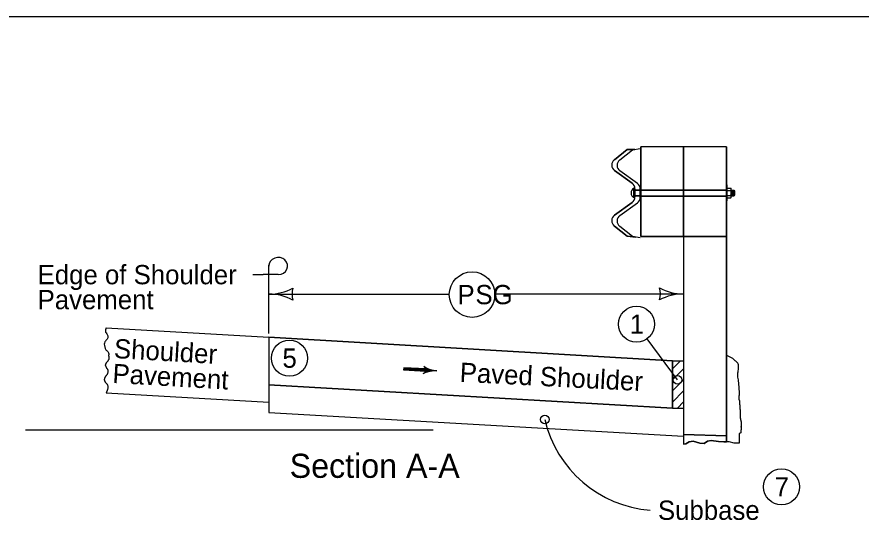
# Model space of a CAD drawing. Extents: x 8045 to 81668, y 6217 to 16762.
# Drawn here: x 10335 to 11036, y 8939 to 9356 of the extents above; entities that cross this region are included whole.
import ezdxf

# ---------------------------------------------------------------- set-up
doc = ezdxf.new("R2010")
doc.units = 0
for name, color, linetype in [('dsnStdDetailExtension', 7, 'Continuous'), ('dsnStdLabel', 7, 'Continuous'), ('dsnStdLineWork', 7, 'Continuous'), ('dsnStdPattern', 7, 'Continuous'), ('Level 4', 7, 'Continuous'), ('Level 8', 7, 'Continuous'), ('TextBlockOut', 7, 'Continuous')]:
    doc.layers.add(name, color=color, linetype=linetype)

msp = doc.modelspace()

# ---------------------------------------------------------------- linework, layer by layer
at = {"layer": 'dsnStdDetailExtension'}
msp.add_circle((10773.25, 9022.18), 3.54, dxfattribs=at)
msp.add_circle((10773.25, 9022.18), 3.54, dxfattribs=at)
at = {"layer": 'dsnStdLabel'}
for p, q in [((10924.05, 9248.59), (10852.96, 9248.59)), ((10852.96, 9173.94), (10852.96, 9248.59)), ((10888.5, 9173.94), (10888.5, 9248.59)), ((10924.05, 9248.59), (10924.05, 9003.55)), ((10831.02, 9237.83), (10841.78, 9246.23)), ((10835.45, 9237.6), (10846.22, 9246.01)), ((10841.78, 9246.23), (10848.11, 9246.34)), ((10846.22, 9246.01), (10852.56, 9247.12)), ((10845.72, 9218.29), (10831.21, 9228.71)), ((10850.19, 9218.06), (10835.63, 9228.51)), ((10847.34, 9206.19), (10847.34, 9214.27)), ((10848.12, 9206.85), (10848.11, 9213.66)), ((10852.56, 9210.04), (10852.56, 9213.44)), ((10924.05, 9216.88), (10924.73, 9216.88)), ((10924.73, 9203.55), (10924.73, 9216.88)), ((10924.73, 9214.26), (10927.7, 9214.26)), ((10847.34, 9212.58), (10852.77, 9212.58)), ((10847.34, 9207.91), (10852.96, 9207.91)), ((10848.11, 9206.85), (10848.12, 9210.26)), ((10848.12, 9210.26), (10848.12, 9206.85)), ((10848.29, 9212.58), (10852.96, 9212.58)), ((10852.56, 9206.63), (10852.56, 9210.04)), ((10852.56, 9210.04), (10852.56, 9206.63)), ((10852.95, 9207.58), (10924.05, 9207.58)), ((10852.96, 9212.91), (10924.05, 9212.91)), ((10852.96, 9212.58), (10924.05, 9212.58)), ((10852.96, 9207.91), (10924.05, 9207.91)), ((10924.73, 9212.24), (10927.7, 9212.24)), ((10924.73, 9208.2), (10927.7, 9208.2)), ((10928.06, 9207.19), (10928.06, 9213.25)), ((10928.06, 9212.55), (10930.43, 9212.55)), ((10928.06, 9207.89), (10930.43, 9207.89)), ((10928.95, 9212.55), (10928.95, 9207.89)), ((10929.69, 9212.55), (10929.69, 9207.89)), ((10930.43, 9212.55), (10930.88, 9212.02)), ((10930.43, 9212.55), (10930.43, 9207.89)), ((10930.88, 9208.42), (10930.43, 9207.89)), ((10930.88, 9212.02), (10930.88, 9208.42)), ((10831.21, 9191.8), (10845.72, 9202.22)), ((10835.63, 9191.56), (10850.19, 9202.02)), ((10924.05, 9203.55), (10924.73, 9203.55)), ((10924.73, 9206.18), (10927.7, 9206.18)), ((10841.78, 9174.29), (10831.02, 9182.68)), ((10846.22, 9174.07), (10835.45, 9182.48)), ((10848.88, 9173.6), (10841.78, 9174.29)), ((10852.56, 9172.95), (10846.22, 9174.07)), ((10888.5, 9173.94), (10852.96, 9173.94)), ((10888.5, 9173.94), (10888.5, 9001.71)), ((10408.97, 9098.32), (10544.11, 9090.46)), ((10544.11, 9090.46), (10544.11, 9036.45)), ((10544.11, 9090.46), (10879.25, 9070.97)), ((10879.25, 9064.23), (10885.99, 9070.97)), ((10879.25, 9064.23), (10885.99, 9070.97)), ((10879.25, 9064.23), (10885.99, 9070.97)), ((10879.25, 9064.23), (10885.99, 9070.97)), ((10879.25, 9070.97), (10888.49, 9070.97)), ((10879.25, 9070.97), (10879.25, 9031.55)), ((10879.25, 9055.04), (10888.49, 9064.28)), ((10879.25, 9055.04), (10888.49, 9064.28)), ((10879.25, 9055.04), (10888.49, 9064.28)), ((10879.25, 9055.04), (10888.49, 9064.28)), ((10934.1, 9064.21), (10934.1, 9064.21)), ((10879.25, 9045.82), (10888.49, 9055.05)), ((10879.25, 9045.82), (10888.49, 9055.05)), ((10879.25, 9045.82), (10888.49, 9055.05)), ((10879.25, 9045.82), (10888.49, 9055.05)), ((10879.25, 9031.55), (10544.11, 9050.86)), ((10879.25, 9036.59), (10888.49, 9045.83)), ((10409, 9044.31), (10544.11, 9036.45)), ((10544.11, 9036.45), (10544.11, 9028.03)), ((10879.25, 9031.55), (10888.49, 9031.55)), ((10883.35, 9031.55), (10888.49, 9036.68)), ((10544.11, 9028.03), (10888.5, 9008.17)), ((10342.06, 9013.62), (10680.56, 9013.62))]:
    msp.add_line(p, q, dxfattribs=at)
for points in [[(10928.05, 9207.51), (10928, 9207.78), (10927.96, 9207.95), (10927.87, 9208.11), (10927.75, 9208.2), (10927.83, 9208.3), (10927.91, 9208.52), (10927.97, 9208.83), (10928.05, 9209.58), (10928.05, 9207.51), (10928.03, 9207.65), (10927.99, 9207.87), (10927.91, 9208.08), (10927.79, 9208.19), (10927.83, 9208.28), (10927.89, 9208.42), (10927.99, 9208.93), (10928.03, 9209.31), (10928.03, 9207.7), (10928, 9207.82), (10927.96, 9207.98), (10927.83, 9208.19), (10927.88, 9208.36), (10927.96, 9208.69), (10928.02, 9209.02), (10928.01, 9207.86), (10927.97, 9207.98), (10927.86, 9208.18), (10927.9, 9208.39), (10927.96, 9208.65), (10927.99, 9208.82), (10927.99, 9207.96), (10927.93, 9208.07), (10927.88, 9208.18), (10927.97, 9208.64), (10927.97, 9208.04), (10927.9, 9208.18), (10927.95, 9208.47), (10927.95, 9208.12), (10927.92, 9208.19), (10927.93, 9208.29), (10927.93, 9208.21)], [(10927.76, 9212.24), (10927.83, 9212.28), (10927.91, 9212.39), (10927.99, 9212.61), (10928.05, 9212.89), (10928.05, 9210.95), (10927.99, 9211.46), (10927.94, 9211.83), (10927.82, 9212.16), (10927.76, 9212.24), (10927.82, 9212.25), (10927.92, 9212.39), (10928.01, 9212.62), (10928.03, 9212.77), (10928.03, 9211.24), (10927.96, 9211.73), (10927.9, 9211.99), (10927.8, 9212.22), (10927.83, 9212.23), (10927.97, 9212.45), (10928.01, 9212.6), (10928.01, 9211.49), (10927.82, 9212.21), (10927.99, 9212.48), (10927.99, 9211.63), (10927.85, 9212.19), (10927.97, 9212.42), (10927.98, 9211.78), (10927.87, 9212.18), (10927.96, 9212.35), (10927.96, 9211.94), (10927.89, 9212.16), (10927.94, 9212.28), (10927.94, 9212.08), (10927.91, 9212.15), (10927.92, 9212.19)], [(10934.57, 9040.37), (10934.51, 9040.09), (10934.51, 9039.9), (10934.51, 9039.7), (10934.51, 9039.51), (10934.51, 9039.31), (10934.51, 9039.12), (10934.51, 9038.82), (10934.51, 9038.63), (10934.61, 9038.34), (10934.71, 9038.04), (10934.9, 9037.85), (10934.9, 9037.65), (10935, 9037.46), (10935, 9037.26), (10935, 9037.06), (10935.1, 9036.97), (10935.1, 9036.77), (10935.1, 9036.58), (10935.1, 9036.38), (10935.1, 9036.19), (10935.1, 9035.99), (10935.1, 9035.7), (10935.1, 9035.4), (10935.1, 9035.21), (10935.1, 9034.92), (10935.1, 9034.72), (10935.1, 9034.52), (10935.2, 9034.43), (10935.2, 9034.23), (10935.2, 9034.04), (10935.2, 9033.84), (10935.2, 9033.65), (10935.2, 9033.45), (10935.2, 9033.25), (10935.2, 9033.06), (10935.2, 9032.86), (10935.2, 9032.67), (10935.2, 9032.47), (10935.2, 9032.28), (10935.2, 9032.08), (10935.2, 9031.89), (10935.2, 9031.69), (10935.2, 9031.5), (10935.2, 9031.3), (10935.2, 9031.1), (10935.2, 9030.91), (10935.29, 9030.81), (10935.29, 9030.62), (10935.29, 9030.42), (10935.39, 9030.32), (10935.39, 9030.13), (10935.39, 9029.93), (10935.49, 9029.83), (10935.49, 9029.64), (10935.49, 9029.44), (10935.49, 9029.25), (10935.49, 9028.96), (10935.59, 9028.66), (10935.59, 9028.47), (10935.59, 9028.27), (10935.59, 9028.08), (10935.59, 9027.88), (10935.59, 9027.69), (10935.59, 9027.49), (10935.59, 9027.29), (10935.59, 9027.1), (10935.59, 9026.9), (10935.59, 9026.71), (10935.59, 9026.51), (10935.59, 9026.32), (10935.59, 9026.12), (10935.59, 9025.93), (10935.59, 9025.73), (10935.59, 9025.54), (10935.59, 9025.34), (10935.59, 9025.14), (10935.59, 9024.95), (10935.59, 9024.75), (10935.59, 9024.56), (10935.59, 9024.36), (10935.59, 9024.17), (10935.59, 9023.97), (10935.59, 9023.78), (10935.59, 9023.58), (10935.59, 9023.39), (10935.59, 9023.19), (10935.59, 9023), (10935.68, 9022.9), (10935.68, 9022.6), (10935.68, 9022.41), (10935.78, 9022.21), (10935.88, 9021.92), (10935.88, 9021.73), (10935.98, 9021.63), (10935.98, 9021.43), (10936.07, 9021.33), (10936.17, 9021.24), (10936.17, 9021.04), (10936.17, 9020.85), (10936.17, 9020.65), (10936.27, 9020.55), (10936.27, 9020.36), (10936.27, 9020.16), (10936.27, 9019.97), (10936.27, 9019.77), (10936.27, 9019.58), (10936.27, 9019.38), (10936.27, 9019.19), (10936.27, 9018.99), (10936.27, 9018.79), (10936.27, 9018.6), (10936.27, 9018.4), (10936.27, 9018.21), (10936.27, 9018.01), (10936.27, 9017.82), (10936.27, 9017.62), (10936.27, 9017.43), (10936.27, 9017.23), (10936.27, 9017.04), (10936.27, 9016.84), (10936.27, 9016.64), (10936.27, 9016.45), (10936.27, 9016.25), (10936.27, 9016.06), (10936.27, 9015.86), (10936.27, 9015.67), (10936.27, 9015.67), (10936.27, 9015.96), (10936.27, 9016.16), (10936.27, 9016.35), (10936.27, 9016.16), (10936.27, 9015.96), (10936.27, 9015.77), (10936.27, 9015.57), (10936.27, 9015.37), (10936.27, 9015.18), (10936.27, 9014.98), (10936.27, 9014.79), (10936.27, 9014.59), (10936.27, 9014.4), (10936.27, 9014.2), (10936.27, 9014.01), (10936.27, 9013.81), (10936.27, 9013.62), (10936.27, 9013.42), (10936.17, 9013.32), (10936.17, 9013.13), (10936.17, 9012.93), (10936.17, 9012.74), (10936.17, 9012.54), (10936.17, 9012.35), (10936.17, 9012.15), (10936.17, 9011.95), (10936.17, 9011.76), (10936.17, 9011.56), (10936.17, 9011.37), (10936.07, 9011.27), (10935.98, 9011.08), (10935.88, 9010.98), (10935.78, 9010.88), (10935.68, 9010.78), (10935.49, 9010.68), (10935.29, 9010.68), (10935.2, 9010.59), (10935.1, 9010.49), (10935, 9010.39), (10934.8, 9010.29), (10934.71, 9010.2), (10934.71, 9010), (10934.61, 9009.9), (10934.61, 9009.71), (10934.61, 9009.51), (10934.61, 9009.32), (10934.61, 9002.5)], [(10934.74, 9002.5), (10930.59, 9002.38), (10926.46, 9003.55), (10921.9, 9003.55), (10917.66, 9003.97), (10911.41, 9004.71), (10908.33, 9004.08), (10905.68, 9002.28), (10901.97, 9002.49), (10896.36, 9004.08), (10893.07, 9003.55), (10890.31, 9001.96), (10888.5, 9001.71)]]:
    msp.add_lwpolyline(points, dxfattribs=at)
for centre, radius, start, end in [((10834.49, 9233.34), 5.68, 127.75002, 234.69086), ((10838.94, 9233.12), 5.68, 127.75002, 234.69086), ((10849.42, 9210.24), 4.54, 117.20289, 242.8461), ((10842.44, 9213.66), 5.68, 360, 54.69099), ((10846.88, 9213.44), 5.68, 360, 54.69099), ((10842.44, 9206.85), 5.68, 305.30901, 0), ((10846.88, 9206.63), 5.68, 305.30901, 0), ((10834.49, 9187.17), 5.68, 125.30914, 232.24998), ((10838.94, 9186.95), 5.68, 125.30914, 232.24998)]:
    msp.add_arc(centre, radius, start, end, dxfattribs=at)
for centre in [(10927.7, 9213.25), (10927.7, 9207.19)]:
    msp.add_ellipse(centre, major_axis=(0, -1.01), ratio=0.362258, start_param=6.283156, end_param=9.424748, dxfattribs=at)
for points in [[(10408.97, 9098.32), (10408.47, 9094.72), (10409.51, 9093.21), (10410.38, 9090.92), (10409.77, 9088.86), (10407.86, 9086.48), (10407.34, 9084.58), (10407.86, 9082.28), (10408.73, 9079.91), (10409.77, 9079.2), (10411.16, 9076.66), (10411.15, 9075.82)], [(10409.18, 9058.71), (10409.39, 9058.96), (10409.59, 9059.22), (10409.94, 9059.78), (10410.23, 9060.37), (10410.34, 9060.68), (10410.44, 9060.99), (10410.57, 9061.61), (10410.62, 9062.23), (10410.58, 9062.82), (10410.52, 9063.1), (10410.48, 9063.23), (10410.43, 9063.36), (10410.23, 9063.74), (10409.94, 9064.1), (10409.64, 9064.47), (10409.39, 9064.86), (10409.25, 9065.15), (10409.12, 9065.43), (10408.86, 9066.01), (10408.65, 9066.57), (10408.58, 9066.86), (10408.53, 9067.16), (10408.52, 9067.29), (10408.52, 9067.42), (10408.67, 9068.19), (10408.88, 9068.71), (10409.13, 9069.22), (10409.58, 9069.86), (10410.1, 9070.4), (10410.61, 9070.95), (10410.84, 9071.26), (10411.04, 9071.6), (10411.25, 9072.07), (10411.4, 9072.54), (10411.51, 9073.02), (10411.54, 9073.26), (10411.55, 9073.38), (10411.56, 9073.5), (10411.51, 9074.01), (10411.36, 9074.52), (10411.31, 9074.65), (10411.26, 9074.77), (10411.21, 9074.9), (10411.18, 9075.03), (10411.15, 9075.82)], [(10934.57, 9040.37), (10934.89, 9043.27), (10934.67, 9048.14), (10934.23, 9053.89), (10933.56, 9058.31), (10933.78, 9061.62), (10934.23, 9065.83), (10933.56, 9068.92), (10931.35, 9070.91), (10929.36, 9072.68), (10927.15, 9073.79), (10924.94, 9075.11), (10924.06, 9075.78)], [(10409.18, 9058.71), (10408.97, 9058.47), (10408.72, 9058.24), (10408.49, 9058), (10408.3, 9057.73), (10408.16, 9057.45), (10408.02, 9057.16), (10407.76, 9056.59), (10407.65, 9056.31), (10407.56, 9056.02), (10407.49, 9055.73), (10407.46, 9055.58), (10407.44, 9055.43), (10407.45, 9054.92), (10407.58, 9054.4), (10407.79, 9053.88), (10408.04, 9053.37), (10408.49, 9052.74), (10409.01, 9052.19), (10409.52, 9051.64), (10409.75, 9051.34), (10409.95, 9051), (10410.35, 9050.05), (10410.46, 9049.58), (10410.47, 9049.1), (10410.43, 9048.81), (10410.39, 9048.52), (10410.33, 9048.23), (10410.26, 9047.95), (10409.95, 9046.8), (10409.77, 9046.19), (10409.58, 9045.59), (10409.35, 9045), (10409.22, 9044.71), (10409.08, 9044.42), (10409, 9044.31)]]:
    msp.add_spline(points, degree=3, dxfattribs=at)
at = {"layer": 'dsnStdLineWork'}
for p, q in [((10544.11, 9129.54), (10544.11, 9150.4)), ((10530.74, 9142.39), (10539.43, 9142.39)), ((10551.92, 9142.39), (10539.43, 9142.39)), ((10544.11, 9093.61), (10544.11, 9129.54)), ((10544.11, 9126.22), (10693.94, 9126.22)), ((10731.8, 9126.38), (10888.5, 9126.38)), ((10674.32, 9063.12), (10656.11, 9064.17)), ((10674.21, 9062.18), (10674.21, 9062.18)), ((10674.33, 9064.12), (10674.33, 9064.12))]:
    msp.add_line(p, q, dxfattribs=at)
for points in [[(10674.34, 9064.06), (10656.18, 9065.11), (10656.05, 9063.23), (10674.21, 9062.18), (10674.27, 9063.79), (10656.4, 9064.88), (10656.34, 9063.39), (10673.83, 9062.44), (10673.95, 9063.56), (10656.63, 9064.62), (10656.61, 9063.62), (10673.62, 9062.64), (10673.71, 9063.34), (10656.82, 9064.4), (10656.8, 9063.84), (10673.41, 9062.9)], [(10673.94, 9065.31), (10674.63, 9064.15), (10674.61, 9062.5), (10673.85, 9061.1), (10676.61, 9061.97), (10679.8, 9062.62), (10680.7, 9062.75), (10678.46, 9063.3), (10675.23, 9064.53), (10674.29, 9065.06), (10674.41, 9061.55), (10679.36, 9062.77), (10674.72, 9064.35), (10674.73, 9061.93), (10678.13, 9062.86), (10675.13, 9063.72), (10674.9, 9062.34), (10677.06, 9062.84), (10675.47, 9063.35), (10675.33, 9062.69), (10676.12, 9062.85)]]:
    msp.add_lwpolyline(points, dxfattribs=at)
msp.add_circle((10712.87, 9125.82), 18.93, dxfattribs=at)
for centre, radius, start, end in [((10544.11, 9168.72), 42.5, 270, 298.07249), ((10579.75, 9126.22), 16.42, 162.26665, 197.73335), ((10852.87, 9126.38), 16.42, 342.26665, 17.73335), ((10888.5, 9168.88), 42.5, 241.92751, 270), ((10544.11, 9083.72), 42.5, 61.92751, 90), ((10888.5, 9083.88), 42.5, 90, 118.07249), ((10868.48, 9044.3), 97.76, 193.07698, 265.55799)]:
    msp.add_arc(centre, radius, start, end, dxfattribs=at)
for centre, major_axis, start_param, end_param in [((10551.92, 9149.53), (-7.81, 0), 1.570796, 6.283185), ((10670.55, 9063.33), (3.88, 0), 5.202895, 7.237436), ((10685.61, 9082.75), (-22.17, 0), 0.954258, 1.478381), ((10682.82, 9042.33), (22.17, 0), 1.537172, 2.061295)]:
    msp.add_ellipse(centre, major_axis=major_axis, ratio=0.913811, start_param=start_param, end_param=end_param, dxfattribs=at)
at = {"layer": 'dsnStdPattern'}
for p, q in [((10831.21, 9228.71), (10845.72, 9218.29)), ((10845.72, 9202.22), (10831.21, 9191.8)), ((10879.25, 9070.97), (10544.11, 9090.46)), ((10544.11, 9090.46), (10544.11, 9050.86)), ((10879.25, 9031.55), (10879.25, 9070.97)), ((10544.11, 9050.86), (10879.25, 9031.55))]:
    msp.add_line(p, q, dxfattribs=at)
for points in [[(10888.5, 9212.91), (10888.5, 9248.59), (10852.96, 9248.59), (10852.96, 9212.91), (10852.96, 9212.91), (10888.5, 9212.91)], [(10924.05, 9212.91), (10924.05, 9216.91), (10924.05, 9248.59), (10888.5, 9248.59), (10888.5, 9212.91), (10924.05, 9212.91)], [(10835.46, 9237.61), (10835.45, 9237.6), (10846.22, 9246.01), (10848.11, 9246.34), (10841.78, 9246.23), (10831.02, 9237.83)], [(10850.16, 9218.07), (10850.19, 9218.06), (10835.63, 9228.51), (10835.66, 9228.49)], [(10848.11, 9213.66), (10848.11, 9212.58), (10852.56, 9212.58), (10852.56, 9213.44), (10852.56, 9213.44)], [(10852.56, 9206.63), (10852.56, 9206.63), (10852.56, 9207.91), (10848.12, 9207.91), (10848.12, 9206.85), (10848.12, 9207.91), (10848.11, 9207.91), (10848.11, 9206.85)], [(10852.96, 9212.58), (10852.96, 9207.91), (10852.96, 9207.91), (10888.5, 9207.91), (10888.5, 9212.58), (10852.96, 9212.58), (10852.96, 9212.58)], [(10852.96, 9207.58), (10852.96, 9173.94), (10888.5, 9173.94), (10888.5, 9207.58), (10852.96, 9207.58)], [(10924.05, 9207.91), (10924.05, 9212.58), (10888.5, 9212.58), (10888.5, 9207.91), (10924.05, 9207.91)], [(10924.05, 9173.94), (10924.05, 9203.58), (10924.05, 9207.58), (10888.5, 9207.58), (10888.5, 9173.94), (10924.05, 9173.94)], [(10835.66, 9191.58), (10835.63, 9191.56), (10850.19, 9202.02), (10850.16, 9202)], [(10831.02, 9182.68), (10841.78, 9174.29), (10848.88, 9173.6), (10846.22, 9174.07), (10835.45, 9182.48), (10835.46, 9182.46)], [(10924.05, 9008.6), (10924.05, 9173.94), (10888.5, 9173.94), (10888.5, 9070.97), (10888.5, 9064.28), (10888.5, 9064.28), (10888.5, 9064.28), (10888.5, 9055.05), (10888.5, 9055.05), (10888.5, 9055.05), (10888.5, 9045.91), (10888.5, 9045.91), (10888.5, 9045.91), (10888.5, 9038.98), (10888.5, 9009.76), (10924.05, 9008.6)], [(10924.05, 9008.6), (10888.5, 9009.76), (10888.5, 9001.71), (10890.31, 9001.96), (10893.07, 9003.55), (10896.36, 9004.08), (10901.97, 9002.49), (10905.68, 9002.28), (10908.33, 9004.08), (10911.41, 9004.71), (10917.66, 9003.97), (10921.9, 9003.55), (10924.05, 9003.55), (10924.05, 9008.6)]]:
    msp.add_lwpolyline(points, dxfattribs=at)
msp.add_lwpolyline([(10852.56, 9212.58), (10848.11, 9212.58), (10848.11, 9209.12), (10848.12, 9210.26), (10848.12, 9207.91), (10852.56, 9207.91)], close=True, dxfattribs=at)
for centre, start, end in [((10834.49, 9233.34), 127.75002, 234.69086), ((10838.94, 9233.12), 127.75002, 234.69086), ((10842.44, 9213.66), 0, 54.69099), ((10846.88, 9213.44), 0, 54.69099), ((10842.44, 9206.85), 305.30901, 0), ((10846.88, 9206.63), 305.30901, 0), ((10834.49, 9187.17), 125.30914, 232.24998), ((10838.94, 9186.95), 125.30914, 232.24998)]:
    msp.add_arc(centre, 5.68, start, end, dxfattribs=at)
at = {"layer": 'Level 4'}
for p, q in [((12307.76, 9356.36), (10152.18, 9356.36)), ((10883.56, 9055.15), (10858.18, 9089.07))]:
    msp.add_line(p, q, dxfattribs=at)
at = {"layer": 'Level 8'}
for centre, radius in [((10849.44, 9101.26), 15), ((10561.16, 9073.08), 15), ((10883.56, 9055.15), 3.58), ((10969.88, 8966.21), 15)]:
    msp.add_circle(centre, radius, dxfattribs=at)
at = {"layer": 'TextBlockOut'}
msp.add_circle((10561.16, 9073.08), 15, dxfattribs=at)

# ---------------------------------------------------------------- texts
at = {"layer": 'dsnStdLineWork'}
for s, height, p in [('Edge of Shoulder ', 16, (10352.05, 9134.39)), ('Pavement', 16, (10352.05, 9113.68)), ('P', 16, (10700.74, 9117.82)), ('SG', 16, (10715.66, 9117.82)), ('Section A-A', 20, (10561.37, 8973.69)), ('Subbase', 16, (10867.26, 8938.83))]:
    msp.add_text(s, height=height, dxfattribs=at).set_placement(p)
for s, rotation, p in [('Shoulder', 356.73462, (10415.1, 9073.15)), ('Pavement', 356.73462, (10413.92, 9052.48)), ('Paved Shoulder ', 357.0678, (10702.33, 9053.48))]:
    msp.add_text(s, height=16, rotation=rotation, dxfattribs=at).set_placement(p)
at = {"layer": 'Level 8'}
for s, p in [('1', (10843.82, 9093.26)), ('5', (10555.39, 9065.08)), ('7', (10964.18, 8958.21))]:
    msp.add_text(s, height=16, dxfattribs=at).set_placement(p)

doc.saveas('drawing.dxf')
